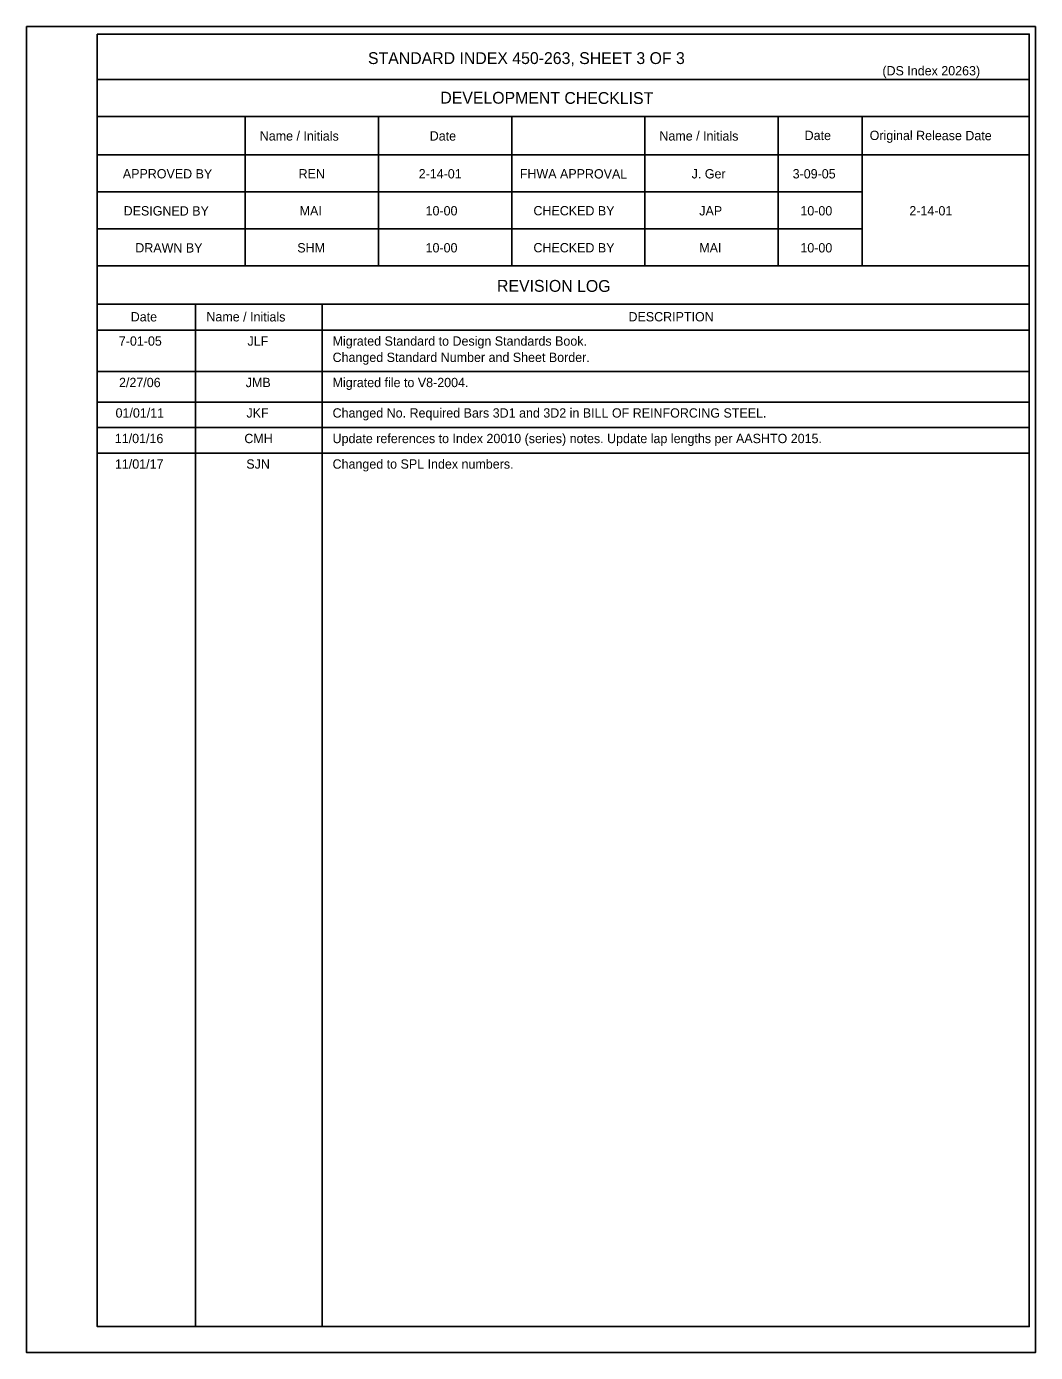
# Model space of a CAD drawing. Extents: x 0 to 54.1, y -6.1 to 22.7.
# Drawn here: x 37.73 to 54.09, y -0.49 to 21.01 of the extents above; entities that cross this region are included whole.
import ezdxf

# ---------------------------------------------------------------- set-up
doc = ezdxf.new("R2010")
doc.units = 0
for name, color, linetype in [('Border', 7, 'Continuous'), ('Dimension', 7, 'Continuous'), ('PlotBorder_dp', 7, 'Continuous'), ('TextStructures', 7, 'Continuous')]:
    doc.layers.add(name, color=color, linetype=linetype)

msp = doc.modelspace()

# ---------------------------------------------------------------- linework, layer by layer
at = {"layer": 'Border'}
for p, q in [((53.991, 20.153), (38.881, 20.153)), ((53.991, 19.553), (38.881, 19.553)), ((41.281, 19.553), (41.281, 17.132)), ((43.441, 19.553), (43.441, 17.132)), ((45.601, 19.553), (45.601, 17.132)), ((47.761, 19.553), (47.761, 17.132)), ((49.921, 19.553), (49.921, 17.132)), ((51.282, 19.553), (51.282, 17.132)), ((53.991, 18.932), (38.881, 18.932)), ((51.282, 18.332), (38.881, 18.332)), ((51.282, 17.732), (38.881, 17.732)), ((53.991, 17.132), (38.881, 17.132)), ((53.991, 16.511), (38.881, 16.511)), ((40.471, 16.511), (40.471, -0.069)), ((42.528, 16.511), (42.528, -0.069)), ((53.991, 16.088), (38.881, 16.088))]:
    msp.add_line(p, q, dxfattribs=at)
msp.add_lwpolyline([(38.881, 20.888), (53.991, 20.888), (53.991, -0.069), (38.881, -0.069)], close=True, dxfattribs=at)
at = {"layer": 'Dimension'}
for p, q in [((38.881, 15.416), (53.991, 15.416)), ((38.881, 14.922), (53.991, 14.922)), ((38.881, 14.509), (53.991, 14.509)), ((38.881, 14.095), (53.991, 14.095))]:
    msp.add_line(p, q, dxfattribs=at)
at = {"layer": 'PlotBorder_dp'}
msp.add_line((37.733, -0.49), (37.733, -0.49), dxfattribs=at)
msp.add_lwpolyline([(37.733, 21.01), (54.093, 21.01), (54.093, -0.49), (37.733, -0.49)], close=True, dxfattribs=at)

# ---------------------------------------------------------------- texts
at = {"layer": 'TextStructures'}
for s, height, p in [('STANDARD INDEX 450-263, SHEET 3 OF 3', 0.192, (43.27, 20.402)), ('(DS Index 20263)', 0.1512, (51.611, 20.218)), ('REN', 0.1512, (42.145, 18.547)), ('2-14-01', 0.1512, (44.092, 18.547)), ('J. Ger', 0.1512, (48.518, 18.547)), ('3-09-05', 0.1512, (50.156, 18.547)), ('MAI', 0.1512, (42.162, 17.947)), ('10-00', 0.1512, (44.204, 17.947)), ('JAP', 0.1512, (48.642, 17.947)), ('10-00', 0.1512, (50.281, 17.947)), ('2-14-01', 0.1512, (52.048, 17.947)), ('SHM', 0.1512, (42.124, 17.347)), ('10-00', 0.1512, (44.204, 17.347)), ('MAI', 0.1512, (48.642, 17.347)), ('10-00', 0.1512, (50.281, 17.347)), ('DESCRIPTION', 0.1512, (47.494, 16.229)), ('7-01-05', 0.1512, (39.23, 15.835)), ('JLF', 0.1512, (41.316, 15.835)), ('Migrated Standard to Design Standards Book.', 0.1512, (42.696, 15.835)), ('Changed Standard Number and Sheet Border.', 0.1512, (42.696, 15.571)), ('2/27/06', 0.1512, (39.233, 15.163)), ('JMB', 0.1512, (41.288, 15.163)), ('Migrated file to V8-2004.', 0.1512, (42.696, 15.163)), ('01/01/11', 0.1512, (39.177, 14.669)), ('JKF', 0.1512, (41.299, 14.669)), ('Changed No. Required Bars 3D1 and 3D2 in BILL OF REINFORCING STEEL.', 0.1512, (42.696, 14.669)), ('11/01/16', 0.1512, (39.165, 14.255)), ('CMH', 0.1512, (41.265, 14.255)), ('Update references to Index 20010 (series) notes. Update lap lengths per AASHTO 2015.', 0.1512, (42.696, 14.255)), ('11/01/17', 0.1512, (39.167, 13.841)), ('SJN', 0.1512, (41.297, 13.841)), ('Changed to SPL Index numbers.', 0.1512, (42.696, 13.841))]:
    msp.add_text(s, height=height, dxfattribs=at).set_placement(p)
for s, height, p in [('DEVELOPMENT CHECKLIST', 0.192, (44.443, 19.761)), ('Name / Initials', 0.1512, (41.515, 19.162)), ('Date', 0.1512, (44.271, 19.161)), ('Name / Initials', 0.1512, (47.995, 19.162)), ('Date', 0.1512, (50.35, 19.17)), ('Original Release Date', 0.1512, (51.405, 19.17)), ('APPROVED BY', 0.1512, (39.295, 18.549)), ('FHWA APPROVAL', 0.1512, (45.732, 18.549)), ('DESIGNED BY', 0.1512, (39.308, 17.947)), ('CHECKED BY', 0.1512, (45.953, 17.949)), ('DRAWN BY', 0.1512, (39.497, 17.347)), ('CHECKED BY', 0.1512, (45.953, 17.349)), ('REVISION LOG', 0.192, (45.362, 16.711)), ('Date', 0.1512, (39.423, 16.229)), ('Name / Initials', 0.1512, (40.65, 16.23))]:
    msp.add_text(s, height=height, rotation=359.8756, dxfattribs=at).set_placement(p)

doc.saveas('drawing.dxf')
